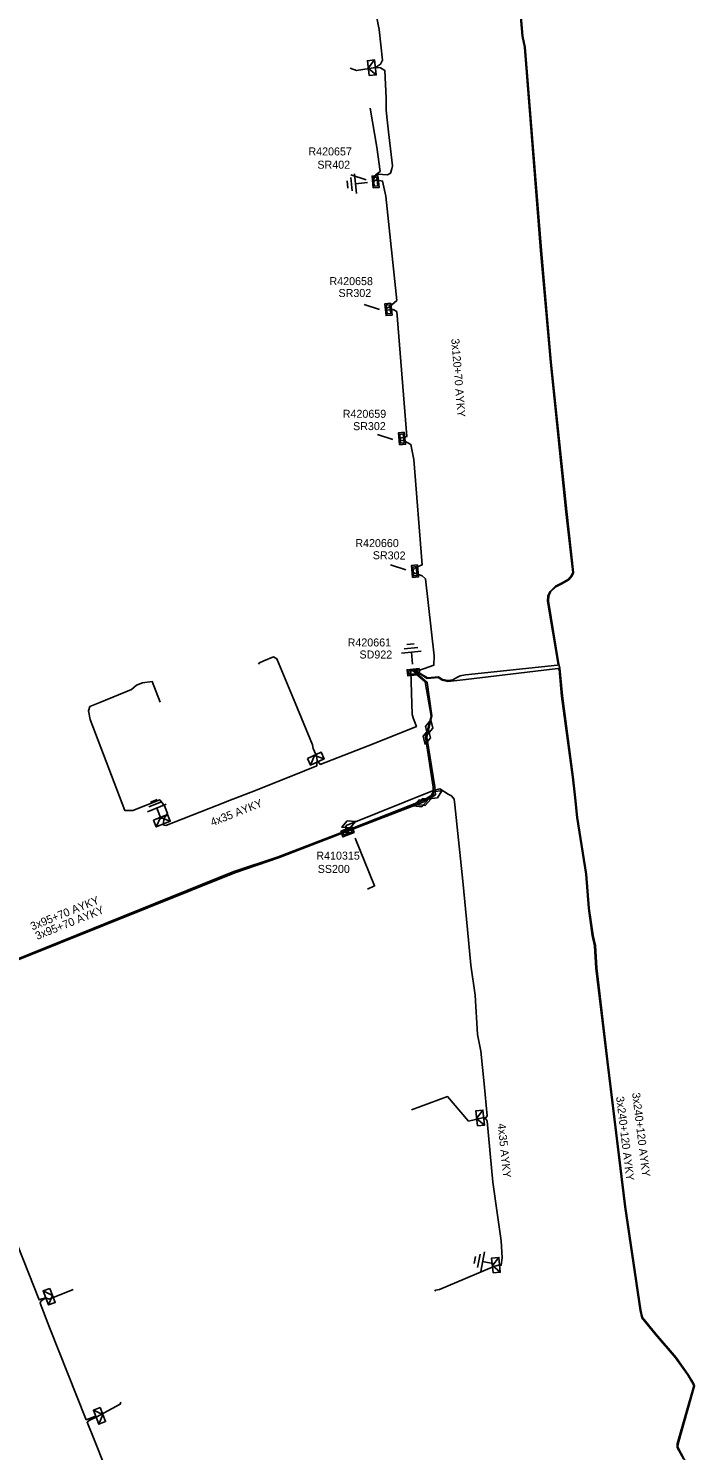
# Model space of a CAD drawing. Extents: x -540028 to -538776, y -1157064 to -1155670.
# Drawn here: x -539686.8 to -539603.5, y -1156356.7 to -1156179 of the extents above; entities that cross this region are included whole.
import ezdxf

# ---------------------------------------------------------------- set-up
doc = ezdxf.new("R2010")
doc.units = 0
for name, color, linetype in [('Vrstva 15', 7, 'Continuous'), ('Vrstva 19', 7, 'Continuous'), ('Vrstva 2', 7, 'Continuous'), ('Vrstva 28', 7, 'Continuous'), ('Vrstva 29', 7, 'Continuous'), ('Vrstva 30', 7, 'Continuous'), ('Vrstva 31', 7, 'Continuous'), ('Vrstva 5', 7, 'Continuous'), ('Vrstva 52', 7, 'Continuous'), ('Vrstva 59', 7, 'Continuous'), ('Vrstva 6', 7, 'Continuous'), ('Vrstva 9', 7, 'Continuous')]:
    doc.layers.add(name, color=color, linetype=linetype)

# ---------------------------------------------------------------- blocks, each defined once
blk = doc.blocks.new('17')
at = {"layer": 'Vrstva 2'}
blk.add_lwpolyline([(-1.875, 0), (0, 0.9375), (1.875, 0), (0, -0.9375)], close=True, dxfattribs=at)
blk = doc.blocks.new('132')
at = {"layer": 'Vrstva 2'}
for points in [[(-1.5, 1.5), (1.5, 1.5), (1.5, 0), (-1.5, 0)], [(-1.1, 1.2), (1.1, 1.2), (1.1, 0.3), (-1.1, 0.3)]]:
    blk.add_lwpolyline(points, close=True, dxfattribs=at)
blk = doc.blocks.new('23')
at = {"layer": 'Vrstva 2'}
blk.add_lwpolyline([(1.875, -1.8), (-1.875, -1.8), (-1.875, 0), (1.875, 0)], close=True, dxfattribs=at)
blk.add_lwpolyline([(1.875, 0), (0, -1.8), (-1.875, 0)], dxfattribs=at)
blk = doc.blocks.new('11')
at = {"layer": 'Vrstva 2'}
for p, q in [((0, -4.3), (0, -1.3)), ((-2.5, -4.3), (2.5, -4.3)), ((-1.7, -5.3), (1.7, -5.3)), ((-0.9, -6.3), (0.9, -6.3))]:
    blk.add_line(p, q, dxfattribs=at)

msp = doc.modelspace()

# ---------------------------------------------------------------- linework, layer by layer
at = {"layer": 'Vrstva 5'}
for points in [[(-539626.21, -1156166.54), (-539625.08, -1156179.95), (-539624.77, -1156181.33), (-539622.75, -1156206.72), (-539621.53, -1156220.71), (-539619.59, -1156239.38), (-539618.74, -1156246.97), (-539618.91, -1156247.35), (-539619.29, -1156247.81), (-539620.14, -1156248.31), (-539620.91, -1156248.7), (-539621.58, -1156249.34), (-539621.84, -1156249.89), (-539621.89, -1156250.56), (-539620.57, -1156258.48), (-539620.66, -1156258.56), (-539632.13, -1156259.76), (-539632.81, -1156259.88), (-539633.21, -1156260.1), (-539633.71, -1156260.39), (-539634.32, -1156260.48), (-539635.03, -1156260.35), (-539635.53, -1156260.01), (-539636.9, -1156260.13), (-539638.51, -1156259.18), (-539638.65, -1156259.08)], [(-539625.64, -1156171.99), (-539624.98, -1156179.93), (-539624.67, -1156181.31), (-539622.65, -1156206.72), (-539621.43, -1156220.7), (-539619.49, -1156239.36), (-539618.64, -1156246.99), (-539618.83, -1156247.41), (-539619.23, -1156247.89), (-539620.1, -1156248.39), (-539620.85, -1156248.78), (-539621.5, -1156249.4), (-539621.74, -1156249.91), (-539621.79, -1156250.56), (-539620.47, -1156258.46), (-539620.34, -1156258.94), (-539620.03, -1156262.4), (-539618.69, -1156272.53), (-539618.39, -1156275.14), (-539618.13, -1156277.59), (-539617.01, -1156284.67), (-539616.67, -1156288.92), (-539616.2, -1156292.33), (-539615.91, -1156293.59), (-539615.75, -1156296.44), (-539614.35, -1156308.12), (-539612.13, -1156326.21), (-539610.22, -1156339.17), (-539610.01, -1156340.09), (-539608.35, -1156342.11), (-539605.81, -1156345.08), (-539604.34, -1156347.15), (-539603.63, -1156348.27), (-539603.52, -1156348.62), (-539605.58, -1156355.87), (-539605.59, -1156356.29), (-539603.61, -1156360.08)], [(-539643.8, -1156197.6), (-539643.13, -1156197.19), (-539641.9, -1156197.26), (-539641.52, -1156197.07), (-539641.34, -1156196.54), (-539641.28, -1156196.15), (-539641.78, -1156191.89), (-539641.98, -1156190.01), (-539642.05, -1156189.16), (-539642.07, -1156187.68), (-539642.24, -1156184.23), (-539642.77, -1156183.9), (-539643.4, -1156183.85), (-539642.77, -1156183.45), (-539642.53, -1156182.93), (-539642.93, -1156179.1), (-539643.33, -1156177.03)], [(-539642.12, -1156214.03), (-539641.62, -1156213.78), (-539640.72, -1156212.97), (-539642.1, -1156199.96), (-539642.51, -1156198.06), (-539643.26, -1156197.89), (-539643.72, -1156198.17)], [(-539640.44, -1156230.23), (-539639.47, -1156229.96), (-539640.71, -1156214.36), (-539641.17, -1156214.09), (-539642.11, -1156214.18)], [(-539638.81, -1156246.77), (-539638.35, -1156246.35), (-539637.57, -1156246.03), (-539638.6, -1156232.86), (-539638.96, -1156230.96), (-539639.81, -1156230.5), (-539640.42, -1156230.39)], [(-539638.35, -1156259.05), (-539638.2, -1156259.12), (-539637.88, -1156259.18), (-539637.25, -1156258.97), (-539636.1, -1156258.57), (-539636.07, -1156257.4), (-539637.12, -1156247.78), (-539637.54, -1156247.39), (-539638.79, -1156246.94)], [(-539639.07, -1156259.12), (-539638.97, -1156259.29), (-539638.79, -1156264.7), (-539638.65, -1156265.25), (-539638.28, -1156266.2), (-539643.56, -1156268.33), (-539650.29, -1156270.96), (-539650.5, -1156270.68), (-539650.66, -1156270.65), (-539650.73, -1156270.77), (-539650.71, -1156271.12), (-539652.28, -1156271.77), (-539658.4, -1156274.2), (-539661.74, -1156275.5), (-539662.03, -1156275.65), (-539665.35, -1156276.91), (-539669.59, -1156278.58), (-539669.86, -1156278.53), (-539669.91, -1156278.41)], [(-539646.63, -1156279.68), (-539646.87, -1156279.16), (-539644.88, -1156278.38), (-539637.4, -1156275.43), (-539636.15, -1156274.69), (-539636.19, -1156273.81), (-539637.14, -1156267.57), (-539636.78, -1156266.2), (-539636.45, -1156264.93), (-539637.18, -1156260.65), (-539638.36, -1156259.64), (-539638.94, -1156259.11)], [(-539636.69, -1156266.32), (-539636.36, -1156264.87), (-539636.93, -1156260.72), (-539638.32, -1156259.52), (-539638.82, -1156259.1)], [(-539604.9, -1156357.76), (-539605.69, -1156356.31), (-539605.68, -1156355.85), (-539603.62, -1156348.62), (-539603.73, -1156348.31), (-539604.42, -1156347.21), (-539605.89, -1156345.14), (-539608.43, -1156342.17), (-539610.11, -1156340.13), (-539610.32, -1156339.19), (-539612.23, -1156326.23), (-539614.45, -1156308.14), (-539615.85, -1156296.44), (-539616.01, -1156293.61), (-539616.3, -1156292.35), (-539616.77, -1156288.93), (-539617.11, -1156284.69), (-539618.23, -1156277.61), (-539618.49, -1156275.15), (-539618.79, -1156272.55), (-539620.13, -1156262.42), (-539620.43, -1156259.06), (-539620.62, -1156258.98), (-539632.08, -1156260.36), (-539634.34, -1156260.58), (-539635.07, -1156260.45), (-539635.55, -1156260.11), (-539636.92, -1156260.23), (-539638.51, -1156259.18), (-539638.64, -1156259.08)], [(-539636.97, -1156267.54), (-539636.69, -1156266.32)], [(-539637.34, -1156275.65), (-539635.9, -1156274.75), (-539635.98, -1156273.78), (-539636.97, -1156267.54)], [(-539627.89, -1156333.5), (-539627.92, -1156333.61), (-539627.67, -1156333.53), (-539627.57, -1156332.62), (-539627.69, -1156330.49), (-539628.13, -1156327.3), (-539628.72, -1156323.17), (-539629.42, -1156315.53), (-539629.58, -1156315.29), (-539629.75, -1156315.24), (-539629.86, -1156315.1), (-539629.59, -1156315.12), (-539629.43, -1156314.89), (-539629.81, -1156310.88), (-539630.23, -1156306.79), (-539630.64, -1156304.7), (-539630.94, -1156299.81), (-539631.46, -1156296.05), (-539631.89, -1156291.6), (-539632.46, -1156285.57), (-539633.49, -1156276.02), (-539633.56, -1156275.29), (-539633.9, -1156274.87), (-539634.31, -1156274.66), (-539635.33, -1156274.01), (-539636.07, -1156274.19), (-539646.74, -1156278.45)], [(-539713.64, -1156306.09), (-539709.48, -1156304.1), (-539701.5, -1156301.17), (-539700.17, -1156300.47), (-539688.46, -1156295.54), (-539660.98, -1156284.52), (-539655.52, -1156282.63), (-539647.32, -1156279.46), (-539637.77, -1156275.82)], [(-539637.77, -1156275.82), (-539637.34, -1156275.65)], [(-539713.7, -1156305.93), (-539709.54, -1156303.92), (-539701.45, -1156300.9), (-539700.08, -1156300.16), (-539688.52, -1156295.42), (-539661.09, -1156284.36), (-539655.55, -1156282.49), (-539647.32, -1156279.34), (-539647.14, -1156279.27), (-539646.88, -1156279.78)], [(-539646.74, -1156278.45), (-539646.99, -1156278.55), (-539647.14, -1156278.77), (-539647.03, -1156279.18), (-539646.76, -1156279.73)], [(-539690.86, -1156324.16), (-539685.43, -1156337.88), (-539685.21, -1156337.8), (-539684.59, -1156337.64), (-539685.19, -1156338.05), (-539685.29, -1156338.3), (-539684.13, -1156341.32), (-539679.54, -1156352.85), (-539678.46, -1156352.46), (-539678.3, -1156352.54), (-539679.15, -1156352.94), (-539679.42, -1156353.18), (-539678.54, -1156355.32), (-539674.6, -1156365.29)]]:
    msp.add_lwpolyline(points, dxfattribs=at)
at = {"layer": 'Vrstva 52'}
for points in [[(-539643.4, -1156183.85), (-539645.77, -1156184.22), (-539646.55, -1156183.93)], [(-539650.66, -1156270.65), (-539650.74, -1156270.03), (-539651.16, -1156268.97), (-539651.26, -1156268.51), (-539653.41, -1156263.26), (-539653.85, -1156262.25), (-539655.7, -1156257.75), (-539656.13, -1156257.5), (-539657.33, -1156258.01), (-539657.89, -1156258.25), (-539657.99, -1156258.43)], [(-539669.91, -1156278.41), (-539669.81, -1156277.68), (-539669.4, -1156277.09), (-539669.77, -1156276.13), (-539670.35, -1156275.38), (-539673.72, -1156276.71), (-539674.71, -1156276.73), (-539679.06, -1156265.33), (-539679.24, -1156264.25), (-539679.07, -1156263.73), (-539677.83, -1156263.21), (-539673.89, -1156261.61), (-539673.25, -1156261.04), (-539672.51, -1156260.75), (-539671.29, -1156260.6), (-539670.28, -1156263.19)], [(-539645.91, -1156280.18), (-539643.51, -1156286.15), (-539644.4, -1156286.53)], [(-539629.86, -1156315.1), (-539631.75, -1156315.53), (-539634.38, -1156312.48), (-539638.87, -1156314.14)], [(-539627.89, -1156333.5), (-539628.6, -1156333.72), (-539635.4, -1156336.56), (-539635.91, -1156336.67), (-539635.96, -1156336.8)], [(-539684.59, -1156337.64), (-539684.17, -1156337.78), (-539681.18, -1156336.59)], [(-539678.3, -1156352.54), (-539675.28, -1156350.93), (-539675.22, -1156350.64)]]:
    msp.add_lwpolyline(points, dxfattribs=at)
at = {"layer": 'Vrstva 59'}
for points in [[(-539644.56, -1156197.9), (-539646.47, -1156197.26)], [(-539642.9, -1156214.12), (-539644.81, -1156213.49)], [(-539641.22, -1156230.35), (-539643.13, -1156229.71)], [(-539639.6, -1156246.65), (-539641.51, -1156246.01)]]:
    msp.add_lwpolyline(points, dxfattribs=at)
at = {"layer": 'Vrstva 9'}
msp.add_lwpolyline([(-539643.74, -1156197.99), (-539643.32, -1156197.22), (-539642.79, -1156196.86), (-539643.23, -1156193.84), (-539644.07, -1156188.94)], dxfattribs=at)

# ---------------------------------------------------------------- block references
at = {"layer": 'Vrstva 15'}
for p, xscale, yscale, rotation in [((-539643.75, -1156198.17), 0.5, 0.5, -84.2356945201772), ((-539638.69, -1156259.06), 0.49999999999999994, 0.49999999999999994, -174.16853339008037), ((-539669.91, -1156278.41), 0.5, 0.5, -157.7508527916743), ((-539627.89, -1156333.5), 0.5, 0.49999999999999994, -101.12726669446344)]:
    msp.add_blockref('11', p, dxfattribs=dict(at, xscale=xscale, yscale=yscale, rotation=rotation))
at = {"layer": 'Vrstva 19', "xscale": 0.5, "yscale": 0.5}
for p, rotation in [((-539636.69, -1156266.32), -102.83556953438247), ((-539636.97, -1156267.54), 77.16443049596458), ((-539635.9, -1156274.75), -147.79467027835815), ((-539637.77, -1156275.82), 20.866481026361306), ((-539637.34, -1156275.65), -159.1335189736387), ((-539646.74, -1156278.45), -158.23471234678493)]:
    msp.add_blockref('17', p, dxfattribs=dict(at, rotation=rotation))
at = {"layer": 'Vrstva 28'}
for p, xscale, yscale, rotation in [((-539643.75, -1156198.17), 0.5, 0.5, -84.2356945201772), ((-539642.14, -1156214.13), 0.5000000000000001, 0.4999999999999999, -84.13162776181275), ((-539640.46, -1156230.27), 0.5000000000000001, 0.5, -84.23955560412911), ((-539638.83, -1156246.85), 0.49999999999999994, 0.5000000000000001, -84.16932218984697), ((-539638.69, -1156259.06), 0.49999999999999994, 0.4999999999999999, -174.16853888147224), ((-539646.76, -1156279.73), 0.5000000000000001, 0.4999999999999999, 21.921383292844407)]:
    msp.add_blockref('132', p, dxfattribs=dict(at, xscale=xscale, yscale=yscale, rotation=rotation))
at = {"layer": 'Vrstva 31'}
for p, xscale, yscale, rotation in [((-539643.4, -1156183.85), 0.49999999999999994, 0.5000000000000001, -83.62473180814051), ((-539650.66, -1156270.65), 0.5000000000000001, 0.5, -155.7990916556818), ((-539669.91, -1156278.41), 0.5, 0.5, -157.7508527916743), ((-539629.86, -1156315.1), 0.5, 0.5, -84.01187221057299), ((-539627.89, -1156333.5), 0.5, 0.5000000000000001, -84.71725829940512), ((-539684.59, -1156337.64), 0.49999999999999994, 0.5000000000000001, 111.037511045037), ((-539678.3, -1156352.54), 0.5, 0.49999999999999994, 111.03751115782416)]:
    msp.add_blockref('23', p, dxfattribs=dict(at, xscale=xscale, yscale=yscale, rotation=rotation))

# ---------------------------------------------------------------- texts
at = {"layer": 'Vrstva 29'}
for s, rotation, p in [('R420657', 359.968, (-539651.77, -1156194.85)), ('R420661', 0.013, (-539646.87, -1156256.22)), ('R410315', 359.994, (-539650.78, -1156282.86))]:
    msp.add_text(s, height=1, rotation=rotation, dxfattribs=at).set_placement(p)
for s, p in [('R420658', (-539649.14, -1156211.06)), ('R420659', (-539647.48, -1156227.64)), ('R420660', (-539645.91, -1156243.8))]:
    msp.add_text(s, height=1, dxfattribs=at).set_placement(p)
at = {"layer": 'Vrstva 30'}
for s, rotation, p in [('SR402', 359.964, (-539650.65, -1156196.51)), ('SR302', 0.116, (-539648.01, -1156212.55)), ('SR302', 0.208, (-539646.19, -1156229.19)), ('SR302', 359.35, (-539643.73, -1156245.31)), ('SD922', 359.909, (-539645.39, -1156257.72)), ('SS200', 0.031, (-539650.61, -1156284.52))]:
    msp.add_text(s, height=1, rotation=rotation, dxfattribs=at).set_placement(p)
at = {"layer": 'Vrstva 6'}
for s, rotation, p in [('3x120+70 AYKY', 274.559, (-539633.92, -1156217.77)), ('4x35 AYKY', 21.656, (-539663.78, -1156278.7)), ('3x95+70 AYKY', 21.954, (-539686.27, -1156291.71)), ('3x95+70 AYKY', 21.864, (-539685.67, -1156292.9)), ('3x240+120 AYKY', 277, (-539613.33, -1156312.51)), ('3x240+120 AYKY', 277, (-539611.33, -1156312.03)), ('4x35 AYKY', 275.963, (-539628.13, -1156315.87))]:
    msp.add_text(s, height=1, rotation=rotation, dxfattribs=at).set_placement(p)

doc.saveas('drawing.dxf')
